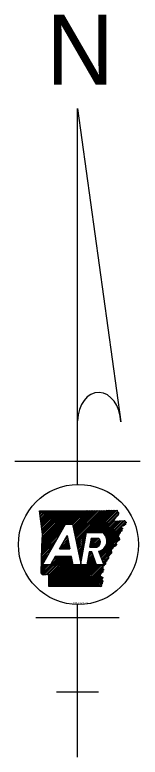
# Model space of a CAD drawing. Extents: x -17742 to 32032, y -17264 to 5867.
# Drawn here: x -7791 to -7528, y -10380 to -8824 of the extents above; entities that cross this region are included whole.
import ezdxf

# ---------------------------------------------------------------- set-up
doc = ezdxf.new("R2010")
doc.units = 0
doc.layers.add('R_Annotation', color=7, linetype='Continuous')

msp = doc.modelspace()

# ---------------------------------------------------------------- linework, layer by layer
at = {"layer": 'R_Annotation'}
for p, q in [((-7659.3, -9020.1), (-7568.4, -9677.2)), ((-7659.3, -9808), (-7659.3, -9020.1)), ((-7790.9, -9759.3), (-7527.8, -9759.3)), ((-7739.1, -9864.5), (-7738, -9863.4)), ((-7738.7, -9867.6), (-7734.6, -9863.4)), ((-7738.4, -9870.7), (-7731.1, -9863.4)), ((-7738, -9873.8), (-7727.6, -9863.4)), ((-7737.6, -9876.9), (-7724.1, -9863.4)), ((-7737.2, -9880), (-7720.6, -9863.4)), ((-7736.8, -9883.1), (-7717.2, -9863.4)), ((-7736.4, -9886.2), (-7713.7, -9863.4)), ((-7736, -9889.3), (-7710.2, -9863.4)), ((-7735.7, -9892.4), (-7706.7, -9863.4)), ((-7735.3, -9895.5), (-7703.2, -9863.4)), ((-7734.9, -9898.6), (-7699.8, -9863.4)), ((-7734.5, -9901.7), (-7696.3, -9863.4)), ((-7734.1, -9904.8), (-7692.8, -9863.4)), ((-7734, -9939.5), (-7657.9, -9863.4)), ((-7733.9, -9935.9), (-7661.4, -9863.4)), ((-7733.8, -9932.3), (-7664.9, -9863.4)), ((-7733.7, -9907.9), (-7689.3, -9863.4)), ((-7733.6, -9928.7), (-7668.4, -9863.4)), ((-7733.5, -9925.1), (-7671.9, -9863.4)), ((-7733.4, -9921.5), (-7675.4, -9863.4)), ((-7733.3, -9917.9), (-7678.8, -9863.4)), ((-7733.3, -9910.9), (-7685.8, -9863.4)), ((-7733.2, -9914.2), (-7682.3, -9863.4)), ((-7682.3, -9891.2), (-7654.4, -9863.4)), ((-7678.8, -9891.2), (-7650.9, -9863.3)), ((-7675.3, -9891.2), (-7647.4, -9863.3)), ((-7671.8, -9891.2), (-7643.9, -9863.3)), ((-7669.7, -9892.5), (-7640.3, -9863.2)), ((-7669, -9895.4), (-7636.8, -9863.2)), ((-7668.4, -9898.3), (-7633.3, -9863.1)), ((-7667.8, -9901.1), (-7629.7, -9863)), ((-7667.2, -9904), (-7626.2, -9863)), ((-7666.6, -9906.9), (-7622.6, -9862.9)), ((-7666, -9909.8), (-7619.1, -9862.9)), ((-7665.4, -9912.6), (-7615.6, -9862.8)), ((-7664.8, -9915.5), (-7612, -9862.8)), ((-7664.1, -9918.4), (-7608.5, -9862.7)), ((-7663.5, -9921.2), (-7605, -9862.7)), ((-7662.9, -9924.1), (-7601.4, -9862.6)), ((-7662.3, -9927), (-7597.9, -9862.5)), ((-7661.7, -9929.8), (-7594.3, -9862.5)), ((-7637.5, -9909.1), (-7590.7, -9862.4)), ((-7634, -9909.1), (-7587.2, -9862.3)), ((-7630.5, -9909.1), (-7583.6, -9862.2)), ((-7627, -9909.1), (-7580, -9862.1)), ((-7623.6, -9909.1), (-7576.5, -9862)), ((-7620.1, -9909.1), (-7575.7, -9864.7)), ((-7616.6, -9909.1), (-7574, -9866.5)), ((-7613.1, -9909.1), (-7573.6, -9869.6)), ((-7734.1, -9943.1), (-7687.1, -9896.1)), ((-7733, -9977), (-7684.4, -9891.2)), ((-7684.4, -9891.2), (-7669.9, -9891.2)), ((-7609.6, -9909.1), (-7581.5, -9881)), ((-7606.5, -9909.4), (-7582.2, -9885.2)), ((-7604.6, -9911), (-7578.5, -9885)), ((-7602.9, -9912.8), (-7574.9, -9884.8)), ((-7601.4, -9914.8), (-7571.2, -9884.6)), ((-7600.1, -9917), (-7567.5, -9884.4)), ((-7599, -9919.4), (-7563.8, -9884.2)), ((-7598.2, -9922.1), (-7560.5, -9884.4)), ((-7597.7, -9925.1), (-7558.9, -9886.3)), ((-7560.5, -9891.3), (-7557.3, -9888.1)), ((-7734.2, -9946.7), (-7691.7, -9904.1)), ((-7640.6, -9909.1), (-7606.9, -9909.1)), ((-7598.4, -9932.8), (-7566.8, -9901.2)), ((-7597.7, -9928.6), (-7567.2, -9898.1)), ((-7570.7, -9908.5), (-7566.4, -9904.2)), ((-7734.5, -9953.9), (-7700.8, -9920.2)), ((-7734.4, -9950.3), (-7696.2, -9912.1)), ((-7697.2, -9943.4), (-7681.3, -9915.3)), ((-7697.1, -9943.4), (-7679.2, -9925.5)), ((-7692.9, -9935.7), (-7679.8, -9922.6)), ((-7688.4, -9927.7), (-7680.4, -9919.7)), ((-7683.8, -9919.7), (-7681, -9916.8)), ((-7661.1, -9932.7), (-7641.3, -9912.9)), ((-7660.5, -9935.6), (-7642, -9917.2)), ((-7659.8, -9938.4), (-7642.8, -9921.4)), ((-7659.2, -9941.3), (-7643.5, -9925.6)), ((-7633.3, -9939.6), (-7615, -9921.2)), ((-7632.6, -9935.4), (-7618.5, -9921.2)), ((-7631.9, -9931.1), (-7621.9, -9921.2)), ((-7631.1, -9926.9), (-7625.4, -9921.2)), ((-7630.4, -9922.7), (-7628.9, -9921.2)), ((-7630.1, -9921.2), (-7614.3, -9921.2)), ((-7629.8, -9939.6), (-7613, -9922.8)), ((-7626.3, -9939.6), (-7611.9, -9925.1)), ((-7612.8, -9954.1), (-7574.2, -9915.5)), ((-7611.9, -9956.7), (-7573.5, -9918.3)), ((-7610.9, -9959.2), (-7572.9, -9921.2)), ((-7610, -9961.7), (-7572.2, -9924)), ((-7601.5, -9939.3), (-7574.9, -9912.7)), ((-7734.7, -9961.1), (-7709.9, -9936.2)), ((-7734.6, -9957.5), (-7705.3, -9928.2)), ((-7693.6, -9943.4), (-7678.5, -9928.3)), ((-7690.1, -9943.4), (-7677.9, -9931.2)), ((-7686.6, -9943.4), (-7677.3, -9934.1)), ((-7683.1, -9943.4), (-7676.7, -9936.9)), ((-7679.6, -9943.4), (-7676.1, -9939.8)), ((-7676.2, -9943.4), (-7675.5, -9942.7)), ((-7658.6, -9944.2), (-7644.2, -9929.8)), ((-7658, -9947.1), (-7645, -9934)), ((-7657.4, -9949.9), (-7645.7, -9938.3)), ((-7656.8, -9952.8), (-7646.5, -9942.5)), ((-7633.3, -9939.6), (-7618.8, -9939.6)), ((-7622.8, -9939.6), (-7611.2, -9927.9)), ((-7619.4, -9939.6), (-7611.5, -9931.7)), ((-7584.1, -9939.4), (-7579.3, -9934.5)), ((-7735, -9968.3), (-7719, -9952.3)), ((-7734.8, -9964.7), (-7714.4, -9944.2)), ((-7697.2, -9943.4), (-7675.3, -9943.4)), ((-7656.2, -9955.7), (-7647.2, -9946.7)), ((-7655.5, -9958.5), (-7647.9, -9950.9)), ((-7654.9, -9961.4), (-7648.7, -9955.1)), ((-7638.5, -9969.4), (-7626.5, -9957.3)), ((-7637.8, -9965.1), (-7627.4, -9954.8)), ((-7637, -9960.9), (-7628.3, -9952.2)), ((-7636.3, -9956.7), (-7629.3, -9949.7)), ((-7635.6, -9952.5), (-7632.8, -9949.7)), ((-7629.2, -9949.7), (-7635.1, -9949.7)), ((-7619.2, -9977), (-7629.2, -9949.7)), ((-7615, -9948.3), (-7604.3, -9977)), ((-7614.7, -9949), (-7613.6, -9948)), ((-7613.8, -9951.6), (-7607.1, -9944.9)), ((-7609.1, -9964.3), (-7588.2, -9943.4)), ((-7608.1, -9966.8), (-7588.6, -9947.3)), ((-7607.2, -9969.4), (-7588.9, -9951.1)), ((-7735.2, -9975.5), (-7728, -9968.3)), ((-7735.1, -9971.9), (-7723.5, -9960.3)), ((-7734.4, -9995.6), (-7697.8, -9959)), ((-7732.4, -9997), (-7694.4, -9959)), ((-7729.9, -9998), (-7690.9, -9959)), ((-7725.7, -9997.4), (-7687.4, -9959)), ((-7722.2, -9997.3), (-7683.9, -9959)), ((-7719.5, -9998.1), (-7680.4, -9959)), ((-7719.4, -10001.4), (-7676.9, -9959)), ((-7719.3, -10004.9), (-7673.5, -9959)), ((-7719.3, -10008.4), (-7671.6, -9960.7)), ((-7719.3, -10011.9), (-7671, -9963.5)), ((-7719.3, -10015.3), (-7670.4, -9966.4)), ((-7719.3, -10018.8), (-7669.8, -9969.3)), ((-7719.2, -10022.2), (-7669.2, -9972.2)), ((-7706.1, -9959), (-7716.3, -9977)), ((-7712.3, -9970.1), (-7701.3, -9959)), ((-7707.8, -9962), (-7704.8, -9959)), ((-7672, -9959), (-7706.1, -9959)), ((-7684.5, -10022.3), (-7624.6, -9962.4)), ((-7681, -10022.3), (-7623.6, -9964.9)), ((-7677.5, -10022.3), (-7622.7, -9967.5)), ((-7674, -10022.3), (-7621.8, -9970)), ((-7670.6, -10022.3), (-7620.8, -9972.6)), ((-7654.3, -9964.3), (-7649.4, -9959.3)), ((-7653.7, -9967.1), (-7650.1, -9963.6)), ((-7653.1, -9970), (-7650.9, -9967.8)), ((-7652.5, -9972.9), (-7651.6, -9972)), ((-7639.2, -9973.6), (-7625.5, -9959.8)), ((-7606.2, -9971.9), (-7595.6, -9961.2)), ((-7605.3, -9974.5), (-7597, -9966.2)), ((-7735.7, -9993.4), (-7719.3, -9977)), ((-7735.7, -9989.9), (-7722.8, -9977)), ((-7735.6, -9986.3), (-7726.3, -9977)), ((-7735.4, -9982.7), (-7729.8, -9977)), ((-7735.3, -9979.1), (-7732.6, -9976.4)), ((-7716.3, -9977), (-7733, -9977)), ((-7715.8, -10022.2), (-7668.6, -9975)), ((-7712.3, -10022.2), (-7667.1, -9977)), ((-7708.8, -10022.2), (-7663.6, -9977)), ((-7705.3, -10022.3), (-7660.1, -9977)), ((-7701.9, -10022.3), (-7656.6, -9977)), ((-7698.4, -10022.3), (-7653.1, -9977)), ((-7694.9, -10022.3), (-7649.7, -9977)), ((-7691.4, -10022.3), (-7646.2, -9977)), ((-7688, -10022.3), (-7642.7, -9977)), ((-7639.8, -9977), (-7668.1, -9977)), ((-7667.1, -10022.3), (-7619.9, -9975.1)), ((-7663.6, -10022.3), (-7618.3, -9977)), ((-7660.1, -10022.3), (-7614.8, -9977)), ((-7656.7, -10022.3), (-7611.4, -9977)), ((-7653.2, -10022.3), (-7607.9, -9977)), ((-7649.7, -10022.3), (-7606.7, -9979.3)), ((-7646.2, -10022.4), (-7606.5, -9982.7)), ((-7642.8, -10022.4), (-7606.4, -9986)), ((-7639.3, -10022.4), (-7606.2, -9989.3)), ((-7604.3, -9977), (-7619.2, -9977)), ((-7635.8, -10022.4), (-7612, -9998.5)), ((-7632.3, -10022.4), (-7610.9, -10000.9)), ((-7628.8, -10022.4), (-7609.8, -10003.3)), ((-7625.4, -10022.4), (-7608.7, -10005.8)), ((-7621.9, -10022.4), (-7607.7, -10008.2)), ((-7618.4, -10022.4), (-7606.8, -10010.7)), ((-7614.9, -10022.4), (-7608.3, -10015.8)), ((-7611.5, -10022.4), (-7609.9, -10020.9)), ((-7659.3, -10379.9), (-7659.3, -10060.1)), ((-7747, -10087.3), (-7571.6, -10087.3)), ((-7703.2, -10243.1), (-7615.4, -10243.1))]:
    msp.add_line(p, q, dxfattribs=at)
for points in [[(-7739.3, -9863.4), (-7691.2, -9863.4), (-7649, -9863.3), (-7599.3, -9862.6), (-7576.2, -9862)], [(-7739.3, -9863.4), (-7691.2, -9863.4), (-7649.1, -9863.3), (-7599.3, -9862.6), (-7576.2, -9862)], [(-7734, -9938.1), (-7733.1, -9912.8), (-7739.3, -9863.4)], [(-7735.8, -9993.4), (-7733.1, -9912.8), (-7739.3, -9863.4)], [(-7669.9, -9891.2), (-7652.1, -9974.7), (-7640.6, -9909.1)], [(-7561.2, -9884.1), (-7557, -9888.5), (-7567.4, -9897), (-7566.2, -9905.6), (-7575.1, -9911.4), (-7572.1, -9924.7), (-7578.9, -9930.9), (-7579.6, -9937.7), (-7587.9, -9940.7), (-7589.2, -9953.5), (-7595.2, -9960), (-7598.1, -9969.6), (-7606.8, -9977.6), (-7606.1, -9991.7), (-7612.1, -9998.3), (-7606.7, -10010.4), (-7610.4, -10022.4)], [(-7583.4, -9885.2), (-7560.8, -9884.1)], [(-7583.4, -9885.2), (-7560.8, -9884.1)], [(-7681.3, -9915.3), (-7675.3, -9943.4)], [(-7633.3, -9939.6), (-7630.1, -9921.2)], [(-7735.8, -9993.4), (-7734, -9938.1)], [(-7635.1, -9949.7), (-7639.8, -9977)], [(-7668.1, -9977), (-7672, -9959)], [(-7610.4, -10022.4), (-7719.3, -10022.2), (-7719.4, -9998.2)], [(-7610.4, -10022.4), (-7719.3, -10022.2), (-7719.3, -9998.2)]]:
    msp.add_lwpolyline(points, dxfattribs=at)
for centre, major_axis, ratio, start_param, end_param in [((-7613.9, -9678.6), (-1.9, 63.2), 0.719778, 4.712385, 7.768526), ((-7619.4, -9927), (-21.8, 0), 0.999987, 1.777838, 4.099264), ((-7622.3, -9929), (-11.1, 0), 0.999987, 1.887169, 3.90762)]:
    msp.add_ellipse(centre, major_axis=major_axis, ratio=ratio, start_param=start_param, end_param=end_param, dxfattribs=at)
msp.add_ellipse((-7657.3, -9934.1), major_axis=(126, 0), ratio=0.999976, dxfattribs=at)
for points in [[(-7576.2, -9862), (-7576.1, -9863.3), (-7575.7, -9864), (-7575.6, -9865.3), (-7575.1, -9865.8), (-7574.2, -9866.4), (-7573.5, -9867.2), (-7573.3, -9868.2), (-7573.6, -9869.2), (-7573.6, -9870.4), (-7573.7, -9871.4), (-7573.9, -9872.3), (-7574.6, -9873.1), (-7575.3, -9873.6), (-7575.9, -9874.2), (-7576.4, -9874.9), (-7577.1, -9875.6), (-7577.9, -9876.4), (-7578.6, -9877), (-7579.2, -9877.8), (-7579.5, -9878.8), (-7580.1, -9879.4), (-7580.7, -9880), (-7581.4, -9880.8), (-7581.7, -9881.6), (-7582.4, -9882.5), (-7582.6, -9883.4), (-7583, -9884.1), (-7583.1, -9884.3)], [(-7576.2, -9862), (-7576.1, -9863.3), (-7575.7, -9864), (-7575.6, -9865.3), (-7575.1, -9865.8), (-7574.3, -9866.3), (-7573.5, -9867.2), (-7573.3, -9868.2), (-7573.5, -9869.3), (-7573.6, -9870.4), (-7573.7, -9871.4), (-7573.9, -9872.3), (-7574.6, -9873.1), (-7575.3, -9873.6), (-7575.9, -9874.3), (-7576.4, -9874.9), (-7577.1, -9875.6), (-7577.9, -9876.4), (-7578.5, -9877), (-7579.2, -9877.8), (-7579.5, -9878.8), (-7580.1, -9879.4), (-7580.7, -9880), (-7581.4, -9880.8), (-7581.7, -9881.6), (-7582.4, -9882.5), (-7582.6, -9883.4), (-7583, -9884.1), (-7583.1, -9884.3)], [(-7561.2, -9884.1), (-7560.8, -9884.1), (-7559.8, -9885.1), (-7559.4, -9886.1), (-7558.7, -9886.5), (-7558, -9886.8), (-7557.4, -9887.5), (-7557, -9888.3), (-7557.2, -9888.9), (-7558.1, -9889), (-7559, -9889.1), (-7559.9, -9889.1), (-7560.6, -9889.7), (-7559.9, -9890.5), (-7559.1, -9891.2), (-7558.8, -9892), (-7559.3, -9892.8), (-7560.3, -9893.2), (-7561.2, -9893.6), (-7562, -9894.3), (-7562.4, -9895), (-7563.3, -9895.3), (-7564.3, -9895.5), (-7565.1, -9895.6), (-7566.1, -9895.8), (-7567, -9896.3), (-7567.4, -9897), (-7567.2, -9898.1), (-7567.3, -9899.3), (-7566.3, -9899.7), (-7565.4, -9899.7), (-7564.6, -9900.1), (-7564.7, -9900.8), (-7565.3, -9901.6), (-7566.1, -9902.3), (-7566.8, -9902.6), (-7567.5, -9903.2), (-7567.2, -9903.9), (-7566.6, -9904.3), (-7566.2, -9904.9), (-7566.2, -9905.6), (-7567, -9906), (-7567.7, -9905.8), (-7568.3, -9905.1), (-7568.9, -9904.9), (-7569.5, -9904.6), (-7570.2, -9905), (-7570.2, -9905.8), (-7570.4, -9906.7), (-7570.2, -9907.4), (-7569.9, -9908.4), (-7570, -9909.1), (-7570.2, -9910.1), (-7570.7, -9911.2), (-7571.3, -9911.5), (-7571.5, -9910.4), (-7571.6, -9909.4), (-7572, -9908.9), (-7572.5, -9908.9), (-7573.1, -9909.3), (-7573.8, -9910), (-7574.6, -9910.7), (-7575.1, -9911.5), (-7574.9, -9912.4), (-7574.2, -9912.6), (-7573.7, -9912.5), (-7573.5, -9911.9), (-7573, -9911.8), (-7572.5, -9912.7)], [(-7572.5, -9912.7), (-7572.3, -9913.6), (-7572.9, -9914.5), (-7573.1, -9915.4), (-7573, -9916.3), (-7573.9, -9916.8), (-7574.7, -9917.4), (-7574.2, -9918.1), (-7573.3, -9918.8), (-7572.5, -9919.3), (-7571.9, -9919.8), (-7571.8, -9921), (-7571.6, -9921.8), (-7571.3, -9922.9), (-7571.2, -9923.6), (-7571.7, -9924.5), (-7572.3, -9924.7), (-7573, -9924.5), (-7573.8, -9924.4), (-7574.4, -9925), (-7574.9, -9925.8), (-7575.3, -9926.7), (-7575.6, -9927.4), (-7576, -9928.2), (-7576.6, -9929.1), (-7577.4, -9929.2), (-7578.4, -9929.4), (-7578.9, -9930.1), (-7578.8, -9931.2), (-7578.3, -9931.9), (-7577.9, -9932.8), (-7577.6, -9933.6), (-7577.7, -9934.7), (-7578.1, -9935.4), (-7578.7, -9935.9), (-7578.9, -9936.8), (-7579.3, -9937.5), (-7579.7, -9937.8), (-7580.4, -9937.7), (-7581.2, -9937.5), (-7581.8, -9937.6), (-7582.4, -9937.9), (-7583.1, -9937.7), (-7583.7, -9937), (-7584.3, -9936.5), (-7584.9, -9936.3), (-7585.5, -9936.6), (-7585.6, -9937.6), (-7585.3, -9938.6), (-7585, -9939.9), (-7585.3, -9940.8), (-7585.4, -9942.2)], [(-7585.4, -9942.2), (-7586.4, -9942.9), (-7586.9, -9943.8), (-7589.5, -9943.5), (-7589.5, -9944.5), (-7590.4, -9944.9), (-7591.2, -9945.5), (-7590.8, -9946.3), (-7589.9, -9946.9), (-7589, -9947.4), (-7588.4, -9947.9), (-7588.3, -9949.2), (-7588.1, -9949.9), (-7587.8, -9951), (-7587.7, -9951.7), (-7588.2, -9952.6), (-7588.9, -9952.8), (-7589.5, -9952.6), (-7590.3, -9952.5), (-7590.9, -9953.1), (-7591.3, -9954), (-7591.8, -9954.8), (-7592.1, -9955.5), (-7592.5, -9956.3), (-7593.1, -9957.2), (-7593.9, -9957.3), (-7594.8, -9957.6), (-7595.4, -9958.2), (-7595.3, -9959.3), (-7594.8, -9960), (-7594.4, -9961), (-7594.1, -9961.8), (-7594.2, -9962.8), (-7594.6, -9963.5), (-7595.2, -9964), (-7595.4, -9964.9), (-7595.8, -9965.6), (-7596.2, -9965.9), (-7596.9, -9965.8), (-7597.6, -9965.7), (-7598.3, -9965.7), (-7598.9, -9966), (-7599.5, -9965.8), (-7600.2, -9965.1), (-7600.7, -9964.6), (-7601.3, -9964.4), (-7602, -9964.7), (-7602.1, -9965.7), (-7601.8, -9966.7), (-7601.5, -9968.1), (-7601.8, -9968.9), (-7601.8, -9970.3)], [(-7601.8, -9970.3), (-7601.9, -9970.3), (-7602.5, -9971), (-7602.2, -9972), (-7601, -9972.5), (-7600.5, -9973.5), (-7600.4, -9974.3), (-7600.8, -9975.6), (-7601.4, -9976.1), (-7602.4, -9976.4), (-7603.2, -9976.5), (-7603.3, -9977.9), (-7603.7, -9978.6), (-7604.3, -9978.8), (-7605.2, -9978.3), (-7605.7, -9978.1), (-7606.4, -9977.8), (-7607.2, -9977.3), (-7607.9, -9977.4), (-7607.7, -9978.7), (-7607.6, -9978.8), (-7606.9, -9979.8), (-7606.2, -9980.5), (-7605.9, -9981.5)], [(-7601.8, -9970.3), (-7601.9, -9970.3), (-7602.5, -9971), (-7602.2, -9972), (-7601, -9972.5), (-7600.5, -9973.5), (-7600.4, -9974.3), (-7600.8, -9975.6), (-7601.4, -9976.1), (-7602.4, -9976.4), (-7603.2, -9976.5), (-7603.3, -9977.9), (-7603.7, -9978.6), (-7604.3, -9978.8), (-7605.2, -9978.3), (-7605.7, -9978.1), (-7606.4, -9977.8), (-7607.2, -9977.3), (-7607.9, -9977.4), (-7607.7, -9978.7), (-7607.6, -9978.8), (-7606.9, -9979.8), (-7606.2, -9980.5), (-7605.9, -9981.5)], [(-7605.9, -9981.5), (-7606.1, -9982.2), (-7606.5, -9983.3), (-7606.4, -9984.3), (-7605.9, -9985.2), (-7605.2, -9985.7), (-7604.4, -9986.4), (-7604.5, -9987.4), (-7605, -9987.8), (-7606, -9987.5), (-7606.8, -9987.2), (-7607.5, -9987.4), (-7608.4, -9987.8), (-7609.1, -9987.9), (-7609.1, -9989.3), (-7608.1, -9990.4), (-7607.3, -9990.4), (-7606.4, -9990.5), (-7606.1, -9991.5), (-7606.6, -9992.4), (-7607.5, -9992.9), (-7608.6, -9992.3), (-7609.4, -9991.8), (-7610.2, -9991.2), (-7611.2, -9991), (-7611.8, -9991.1), (-7612.1, -9992.3), (-7611.6, -9993.5), (-7610.8, -9994.2), (-7610.1, -9995.2), (-7610.2, -9996), (-7610.8, -9996.2), (-7611.7, -9996.4), (-7612.3, -9996.7), (-7612.4, -9996.9), (-7612.1, -9998), (-7611.9, -9999), (-7611.9, -9999.9), (-7612.2, -10000.6), (-7612.7, -10001.8), (-7612.7, -10002.6), (-7612.3, -10003), (-7611.9, -10002.9), (-7611.2, -10002.4), (-7610.9, -10002), (-7610.5, -10001.4), (-7609.9, -10000.9), (-7609.2, -10001.3), (-7609, -10002.2), (-7609.4, -10003), (-7610, -10003.4), (-7610.8, -10003.7), (-7611.4, -10004.3), (-7611.2, -10005.1), (-7610.8, -10005.5), (-7609.7, -10005.3), (-7608.9, -10005), (-7608.5, -10004.6), (-7608, -10004.1), (-7607.8, -10003.6), (-7607.4, -10003), (-7606.7, -10002.9), (-7606.3, -10003.3), (-7606.5, -10004.3), (-7606.9, -10005.3), (-7607.5, -10006.1), (-7608.1, -10006.6), (-7608.9, -10007.9), (-7608.7, -10009), (-7608.4, -10009.9), (-7608, -10010.6), (-7607.3, -10010.5), (-7606.5, -10010.4), (-7606, -10010.8), (-7606.1, -10011.6), (-7606.6, -10012.4), (-7607.2, -10013.2), (-7607.5, -10014.3), (-7607.4, -10015), (-7607.4, -10015.7), (-7607.6, -10016.4), (-7608, -10016.9), (-7609.2, -10016.8), (-7610.3, -10016.7), (-7610.9, -10017.1), (-7610.8, -10018.1), (-7610.1, -10018.8), (-7609.7, -10019.2), (-7609, -10020), (-7608.7, -10020.7), (-7608.8, -10021.3), (-7609.2, -10021.8), (-7610.4, -10022.4)], [(-7605.9, -9981.5), (-7606.1, -9982.2), (-7606.5, -9983.3), (-7606.4, -9984.3), (-7605.9, -9985.2), (-7605.2, -9985.7), (-7604.4, -9986.4), (-7604.5, -9987.4), (-7605, -9987.8), (-7606, -9987.5), (-7606.8, -9987.2), (-7607.5, -9987.4), (-7608.4, -9987.8), (-7609.1, -9987.9), (-7609.1, -9989.3), (-7608.1, -9990.4), (-7607.3, -9990.4), (-7606.4, -9990.5), (-7606.1, -9991.5), (-7606.6, -9992.4), (-7607.5, -9992.9), (-7608.6, -9992.3), (-7609.4, -9991.8), (-7610.2, -9991.2), (-7611.2, -9991), (-7611.8, -9991.1), (-7612.1, -9992.3), (-7611.6, -9993.5), (-7610.8, -9994.2), (-7610.1, -9995.2), (-7610.2, -9996), (-7610.8, -9996.2), (-7611.7, -9996.4), (-7612.3, -9996.7), (-7612.4, -9996.9), (-7612.1, -9998), (-7611.9, -9999), (-7611.9, -9999.9), (-7612.2, -10000.6), (-7612.7, -10001.8), (-7612.7, -10002.6), (-7612.3, -10003), (-7611.9, -10002.9), (-7611.2, -10002.4), (-7610.9, -10002), (-7610.5, -10001.4), (-7609.9, -10000.9), (-7609.2, -10001.3), (-7609, -10002.2), (-7609.4, -10003), (-7610, -10003.4), (-7610.8, -10003.7), (-7611.4, -10004.3), (-7611.2, -10005.1), (-7610.8, -10005.5), (-7609.7, -10005.3), (-7608.9, -10005), (-7608.5, -10004.6), (-7608, -10004.1), (-7607.8, -10003.6), (-7607.4, -10003), (-7606.7, -10002.9), (-7606.3, -10003.3), (-7606.5, -10004.3), (-7606.9, -10005.3), (-7607.5, -10006.1), (-7608.1, -10006.6), (-7608.9, -10007.9), (-7608.7, -10009), (-7608.4, -10009.9), (-7608, -10010.6), (-7607.3, -10010.5), (-7606.5, -10010.4), (-7606, -10010.8), (-7606.1, -10011.6), (-7606.6, -10012.4), (-7607.2, -10013.2), (-7607.5, -10014.3), (-7607.4, -10015), (-7607.4, -10015.7), (-7607.6, -10016.4), (-7608, -10016.9), (-7609.2, -10016.8), (-7610.3, -10016.7), (-7610.9, -10017.1), (-7610.8, -10018.1), (-7610.1, -10018.8), (-7609.7, -10019.2), (-7609, -10020), (-7608.7, -10020.7), (-7608.8, -10021.3), (-7609.2, -10021.8), (-7610.4, -10022.4)], [(-7719.3, -9998.2), (-7719.2, -9998.2), (-7719.8, -9997.9), (-7720.6, -9997.5), (-7721.4, -9997.4), (-7722.5, -9997.3), (-7723.5, -9997.2), (-7724.4, -9996.6), (-7725.4, -9997.2), (-7726.5, -9997.7), (-7727.2, -9997.1), (-7728.1, -9997.5), (-7728.7, -9997.3), (-7729.7, -9998), (-7730.7, -9997.8), (-7731.4, -9998), (-7732.3, -9998), (-7732.5, -9996.9), (-7733.3, -9996.8), (-7734.1, -9996.4), (-7734.6, -9995.3), (-7734.9, -9994.5), (-7735.8, -9993.4)], [(-7719.4, -9998.2), (-7719.2, -9998.3), (-7719.8, -9997.9), (-7720.6, -9997.5), (-7721.4, -9997.4), (-7722.5, -9997.3), (-7723.5, -9997.2), (-7724.4, -9996.6), (-7725.4, -9997.2), (-7726.6, -9997.7), (-7727.2, -9997.2), (-7728.1, -9997.5), (-7728.7, -9997.3), (-7729.7, -9998), (-7730.7, -9997.8), (-7731.4, -9998), (-7732.3, -9998), (-7732.5, -9996.9), (-7733.3, -9996.8), (-7734.1, -9996.4), (-7734.6, -9995.3), (-7734.9, -9994.5), (-7735.8, -9993.4)]]:
    msp.add_spline(points, degree=3, dxfattribs=at)

# ---------------------------------------------------------------- texts
for s, height, p in [('N', 146.7, (-7724.7, -8970.5)), ('STS 10-03-17', 3.644, (-7669.3, -10059.1))]:
    msp.add_text(s, height=height, dxfattribs=at).set_placement(p)

doc.saveas('drawing.dxf')
